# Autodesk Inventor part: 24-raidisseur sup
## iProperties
Created: 2011-02
Part Number: 24-raidisseur sup
Document SubType Name: Modeling
Designer: eric
Density: 1 g/cm^3
Author: eric
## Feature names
1. Base1
